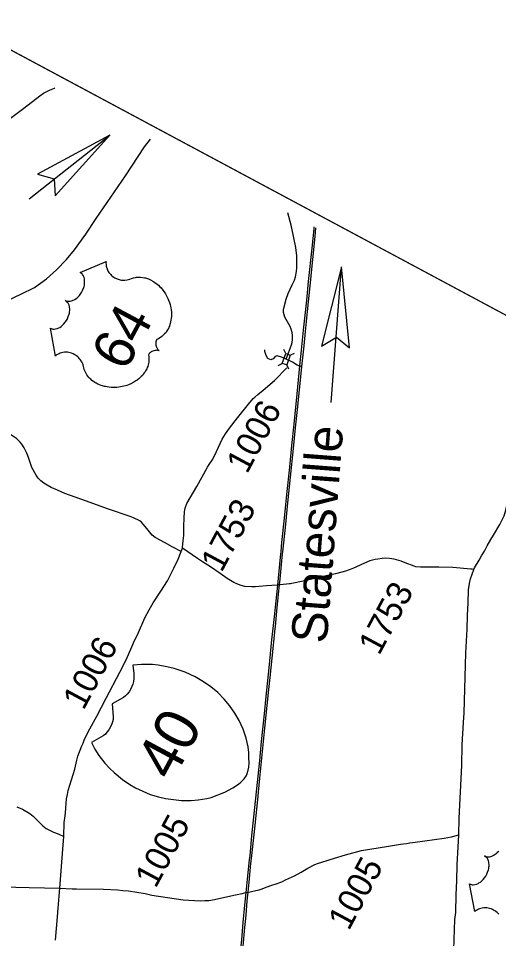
# Model space of a CAD drawing. Extents: x 1376167 to 1379209, y 761324 to 763997.
# Drawn here: x 1376691.6 to 1376772.1, y 762860.1 to 763014.5 of the extents above; entities that cross this region are included whole.
import ezdxf

# ---------------------------------------------------------------- set-up
doc = ezdxf.new("R2010")
doc.units = 0
for name, color, linetype in [('Default', 7, 'Continuous'), ('Old_Level_1', 7, 'Continuous'), ('Prop Terminator CELL', 7, 'Continuous'), ('Sheet Data Field CELL', 7, 'Continuous')]:
    doc.layers.add(name, color=color, linetype=linetype)

msp = doc.modelspace()

# ---------------------------------------------------------------- linework, layer by layer
at = {"layer": 'Default'}
for p, q in [((1376736.39, 762958.25), (1376736.05, 762958.96)), ((1376737.14, 762957.98), (1376737.85, 762958.33)), ((1376735.11, 762956.27), (1376735.82, 762956.62)), ((1376736.92, 762955.64), (1376736.58, 762956.35)), ((1376718.87, 762925.06), (1376719.07, 762925.6))]:
    msp.add_line(p, q, dxfattribs=at)
for points in [[(1376692.48, 762999.48), (1376695.16, 763001.54), (1376695.77, 763001.96), (1376696.79, 763002.5), (1376697.6, 763002.82)], [(1376697.6, 763002.82), (1376697.68, 763002.85)], [(1376672.6, 762984.28), (1376673.27, 762984.79), (1376675.3, 762986.31), (1376676.78, 762987.43), (1376677.83, 762988.21), (1376680.82, 762990.8), (1376686.12, 762994.69), (1376687.79, 762995.97), (1376692.48, 762999.48)], [(1376675.94, 762960.58), (1376682.69, 762963.88), (1376684.96, 762964.96), (1376691.99, 762968.25), (1376694.26, 762969.38), (1376696.28, 762970.78), (1376697.97, 762972.31), (1376699.64, 762974.04), (1376700.98, 762975.67), (1376702.88, 762978.32), (1376704.6, 762980.94), (1376709.52, 762988.1), (1376712.73, 762992.97), (1376713.7, 762994.26)], [(1376736.47, 762957.32), (1376736.87, 762958.38), (1376737.36, 762959.74), (1376737.46, 762960.14), (1376737.52, 762960.65), (1376737.54, 762961.29), (1376737.48, 762961.82), (1376737.31, 762962.36), (1376737.14, 762962.83), (1376736.27, 762964.35), (1376736.11, 762964.78), (1376736.04, 762965.14), (1376736.03, 762965.58), (1376736.07, 762965.9), (1376736.47, 762967.41), (1376736.78, 762968.34), (1376737.47, 762969.82), (1376737.88, 762970.59), (1376738.04, 762971.14), (1376738.2, 762972.06), (1376738.23, 762972.71), (1376738.25, 762974.66), (1376738.11, 762976.06), (1376737.7, 762977.99), (1376737.28, 762979.8), (1376736.75, 762981.9)], [(1376741.12, 762979.56), (1376741.09, 762979.19), (1376740.75, 762975.95), (1376740.18, 762970.34), (1376739.85, 762967.22), (1376739.34, 762962.17), (1376739, 762958.85), (1376738.72, 762956.18)], [(1376739.09, 762956.06), (1376739.46, 762959.54), (1376739.7, 762961.99), (1376740.03, 762965.35), (1376740.47, 762969.66), (1376740.92, 762974.05), (1376741.31, 762977.93), (1376741.46, 762979.38)], [(1376739.13, 762956.03), (1376738.59, 762956.18), (1376738.31, 762956.32), (1376737.52, 762956.8), (1376736.47, 762957.32), (1376735.83, 762957.61), (1376734.97, 762957.86), (1376734.6, 762957.78), (1376734.27, 762957.36), (1376733.92, 762957.2), (1376733.38, 762957.44), (1376733.1, 762957.92), (1376732.89, 762958.61), (1376732.9, 762958.9)], [(1376723.3, 762939.18), (1376723.57, 762939.64), (1376724.15, 762940.55), (1376724.79, 762941.85), (1376725.76, 762943.9), (1376726.3, 762944.79), (1376726.99, 762945.75), (1376728.28, 762947.48), (1376730.17, 762949.79), (1376730.91, 762950.7), (1376731.19, 762950.97), (1376731.73, 762951.38), (1376732.62, 762952.13), (1376734.49, 762953.74), (1376736.57, 762955.88)], [(1376738.72, 762956.18), (1376738.25, 762951.48), (1376737.73, 762946.42), (1376737.37, 762942.83), (1376737, 762939.18), (1376736.54, 762934.6), (1376736.13, 762930.65), (1376735.7, 762926.57), (1376735.55, 762925.07)], [(1376735.91, 762925.01), (1376736.36, 762929.09), (1376736.77, 762933.23), (1376737.2, 762937.51), (1376737.7, 762942.32), (1376738.04, 762945.81), (1376738.36, 762948.89), (1376738.7, 762952.16), (1376739.09, 762956.06)], [(1376769.23, 762924.3), (1376769.71, 762925.09), (1376770.16, 762925.99), (1376770.78, 762927.08), (1376771.24, 762927.77), (1376772.3, 762929.6), (1376773, 762931.02), (1376773.32, 762931.96), (1376774.06, 762935.28), (1376774.5, 762936.86), (1376774.93, 762938.19), (1376775.09, 762938.63), (1376775.39, 762939.28), (1376776.44, 762941.22), (1376776.84, 762942.22), (1376776.93, 762942.61), (1376777.01, 762943.15), (1376777.33, 762945.03), (1376777.55, 762946.64), (1376777.51, 762948.32), (1376777.32, 762949.87), (1376777.12, 762952.07)], [(1376698.1, 762935.36), (1376697.04, 762935.8), (1376696.37, 762936.16), (1376695.83, 762936.5), (1376695.33, 762936.88), (1376694.89, 762937.34), (1376694.52, 762937.85), (1376693.82, 762939.14), (1376693.32, 762940.63), (1376693.1, 762941.29), (1376692.94, 762941.66), (1376692.52, 762942.42), (1376692.15, 762943.04), (1376691.86, 762943.38), (1376691.61, 762943.63), (1376691.41, 762943.82), (1376691.23, 762943.99), (1376690.89, 762944.24), (1376690.28, 762944.6), (1376689.62, 762944.92), (1376687.2, 762945.84)], [(1376719.07, 762925.6), (1376719.1, 762925.79), (1376719.2, 762926.85), (1376719.28, 762927.72), (1376719.3, 762929.28), (1376719.34, 762930.63), (1376719.42, 762931.68), (1376719.45, 762932.02), (1376719.53, 762932.29), (1376719.65, 762932.66), (1376719.83, 762933.11), (1376721.46, 762935.97), (1376723.3, 762939.18)], [(1376718.87, 762925.06), (1376717.36, 762925.83), (1376716.05, 762926.58), (1376715.31, 762926.97), (1376714.5, 762927.4), (1376714.01, 762927.79), (1376713.1, 762928.91), (1376712.49, 762929.63), (1376712.23, 762929.94), (1376711.95, 762930.17), (1376710.89, 762930.71), (1376710.28, 762930.93), (1376706.69, 762932.16), (1376702.81, 762933.54), (1376699.36, 762934.76), (1376698.1, 762935.36)], [(1376710.58, 762909.04), (1376711.05, 762910.1), (1376711.53, 762911.07), (1376712.77, 762913.89), (1376713.47, 762915.24), (1376713.93, 762916.05), (1376714.18, 762916.45), (1376715.42, 762918.39), (1376716.57, 762920.1), (1376717.64, 762922.22), (1376718.35, 762923.78), (1376718.87, 762925.06)], [(1376729.55, 762919.18), (1376728.91, 762919.35), (1376728.17, 762919.61), (1376727.71, 762919.82), (1376726.59, 762920.52), (1376725.41, 762921.37), (1376723.77, 762922.47), (1376722.45, 762923.32), (1376721.58, 762923.87), (1376719.07, 762925.6)], [(1376735.55, 762925.07), (1376735.45, 762924.08), (1376734.99, 762919.41)], [(1376735.34, 762919.43), (1376735.45, 762920.42), (1376735.69, 762922.87), (1376735.87, 762924.64), (1376735.91, 762925.01)], [(1376750.52, 762923.49), (1376749.61, 762923.06), (1376748.26, 762922.48), (1376747.63, 762922.21), (1376746.43, 762921.74), (1376745.82, 762921.59), (1376744.74, 762921.32), (1376743.66, 762921.05), (1376739.31, 762920.09), (1376737.41, 762919.67), (1376737.2, 762919.62)], [(1376755.76, 762923.4), (1376754.57, 762923.77), (1376753.78, 762923.87), (1376753.16, 762923.9), (1376752.58, 762923.85), (1376751.86, 762923.75), (1376751.38, 762923.7), (1376750.52, 762923.49)], [(1376767.95, 762922.03), (1376767.64, 762922.07), (1376767.46, 762922.08), (1376764.44, 762922.36), (1376762.05, 762922.41), (1376760.56, 762922.4), (1376758.97, 762922.41), (1376758.23, 762922.48), (1376757.92, 762922.58), (1376756.44, 762923.13), (1376755.76, 762923.4)], [(1376767.95, 762922.03), (1376768.08, 762922.29), (1376768.81, 762923.58), (1376769.23, 762924.3)], [(1376765.44, 762877.48), (1376765.47, 762880.31), (1376765.9, 762889.15), (1376765.99, 762892.6), (1376766.23, 762896.35), (1376766.3, 762897.96), (1376766.62, 762907.96), (1376766.85, 762911.99), (1376766.87, 762914.3), (1376766.99, 762916.4), (1376767.06, 762918.6), (1376767.22, 762919.69), (1376767.39, 762920.43), (1376767.95, 762922.03)], [(1376733.17, 762919.27), (1376731.3, 762919.1), (1376730.64, 762919.1), (1376729.55, 762919.18)], [(1376734.99, 762919.41), (1376734.05, 762919.35), (1376733.17, 762919.27)], [(1376734.99, 762919.41), (1376734.72, 762916.74), (1376734.46, 762914.09)], [(1376734.65, 762912.47), (1376734.89, 762915.03), (1376735.2, 762917.88), (1376735.34, 762919.43)], [(1376735.34, 762919.43), (1376735.14, 762919.42), (1376734.99, 762919.41)], [(1376737.2, 762919.62), (1376737.04, 762919.6), (1376735.47, 762919.43), (1376735.34, 762919.43)], [(1376734.46, 762914.09), (1376734.02, 762910.24), (1376733.55, 762905.5), (1376733.06, 762900.7), (1376732.78, 762897.78), (1376732.3, 762893.14), (1376731.99, 762889.98), (1376731.43, 762884.7), (1376731.16, 762882.09), (1376730.68, 762877.33), (1376730.35, 762874.02), (1376730.28, 762873.29)], [(1376730.66, 762873.52), (1376731.14, 762878.03), (1376731.64, 762882.86), (1376732.04, 762886.98), (1376732.57, 762892.03), (1376732.91, 762895.4), (1376733.51, 762901.36), (1376733.77, 762903.87), (1376734.1, 762907.15), (1376734.61, 762912.07), (1376734.65, 762912.47)], [(1376704.71, 762897.39), (1376706.28, 762900.44), (1376708.58, 762904.77), (1376709.62, 762906.87), (1376710.58, 762909.04)], [(1376699.18, 762877.2), (1376699.22, 762879.53), (1376699.41, 762880.66), (1376699.44, 762881.2), (1376699.65, 762883.53), (1376699.77, 762884.26), (1376699.93, 762884.95), (1376701.01, 762888.5), (1376701.35, 762890.01), (1376701.54, 762890.67), (1376702.19, 762892.45), (1376702.41, 762892.89), (1376702.67, 762893.53), (1376703.53, 762895.3), (1376704.71, 762897.39)], [(1376691.32, 762882.19), (1376692.22, 762881.79), (1376693.46, 762881.09), (1376694.03, 762880.62), (1376695.64, 762878.99), (1376696.23, 762878.54), (1376697.43, 762877.93), (1376698.22, 762877.68), (1376699.18, 762877.2)], [(1376698.5, 762868.56), (1376698.96, 762874.33), (1376699.18, 762877.2)], [(1376758.08, 762876.23), (1376762.95, 762876.92), (1376764.19, 762877.16), (1376765.44, 762877.48)], [(1376764.9, 762864.43), (1376764.98, 762867.44), (1376765.08, 762869.76), (1376765.14, 762872.49), (1376765.33, 762875.42), (1376765.44, 762877.48)], [(1376741.28, 762872.48), (1376741.91, 762872.72), (1376743.2, 762873.13), (1376743.87, 762873.35), (1376746.4, 762874.12), (1376749.08, 762874.83), (1376749.77, 762874.97), (1376750.85, 762875.15), (1376753.31, 762875.54), (1376754.64, 762875.74), (1376755.65, 762875.91), (1376756.66, 762876.05), (1376757.19, 762876.12), (1376758.08, 762876.23)], [(1376772.15, 762864.15), (1376771.97, 762864.35), (1376771.83, 762864.47), (1376771.65, 762864.61), (1376771.48, 762864.74), (1376771.25, 762864.87), (1376771.06, 762864.97), (1376770.82, 762865.07), (1376770.58, 762865.14), (1376770.36, 762865.19), (1376770.1, 762865.23), (1376769.9, 762865.24), (1376769.62, 762865.23), (1376769.35, 762865.19), (1376769.11, 762865.14), (1376768.89, 762865.07), (1376768.7, 762864.99), (1376768.54, 762864.91), (1376768.35, 762864.8), (1376768.18, 762864.68), (1376768.09, 762864.6), (1376767.24, 762869.26), (1376767.38, 762869.2), (1376767.56, 762869.14), (1376767.65, 762869.12), (1376767.85, 762869.11), (1376768.11, 762869.14), (1376768.38, 762869.21), (1376768.65, 762869.32), (1376768.8, 762869.41), (1376769.04, 762869.56), (1376769.28, 762869.76), (1376769.51, 762870), (1376769.73, 762870.26), (1376769.93, 762870.55), (1376770.1, 762870.86), (1376770.26, 762871.21), (1376770.38, 762871.62), (1376770.43, 762871.81), (1376770.47, 762872.04), (1376770.49, 762872.25), (1376770.49, 762872.51), (1376770.47, 762872.72), (1376770.45, 762872.89), (1376770.38, 762873.15), (1376770.28, 762873.38), (1376770.21, 762873.49), (1376770.15, 762873.59), (1376769.99, 762873.76), (1376769.91, 762873.83), (1376769.74, 762873.94), (1376769.9, 762873.87), (1376770, 762873.83), (1376770.11, 762873.81), (1376770.22, 762873.79), (1376770.4, 762873.79), (1376770.56, 762873.8), (1376770.81, 762873.86), (1376770.94, 762873.9), (1376771.05, 762873.95), (1376771.32, 762874.09), (1376771.6, 762874.28), (1376771.72, 762874.38), (1376771.84, 762874.48), (1376771.98, 762874.62), (1376772.11, 762874.77)], [(1376730.28, 762873.29), (1376730, 762870.59), (1376729.71, 762867.79)], [(1376730.09, 762867.87), (1376730.26, 762869.54), (1376730.56, 762872.66), (1376730.66, 762873.52)], [(1376736.37, 762869.93), (1376737.85, 762870.58), (1376738.99, 762871.24), (1376740.12, 762871.89), (1376741.28, 762872.48)], [(1376733.28, 762868.76), (1376734.08, 762869.06), (1376734.79, 762869.27), (1376735.75, 762869.61), (1376736.37, 762869.93)], [(1376688.9, 762868.78), (1376693.37, 762868.65), (1376698.5, 762868.56)], [(1376697.79, 762859.81), (1376698.12, 762863.72), (1376698.24, 762865.18), (1376698.5, 762868.56)], [(1376698.5, 762868.56), (1376700.58, 762868.42), (1376701.28, 762868.41), (1376705.85, 762868.34), (1376708.24, 762868.28), (1376709.08, 762868.16)], [(1376709.08, 762868.16), (1376710.03, 762868.09), (1376712.83, 762867.62), (1376713.91, 762867.36)], [(1376727.71, 762867.35), (1376729.06, 762867.65), (1376729.71, 762867.79)], [(1376729.71, 762867.79), (1376729.5, 762865.7), (1376729.22, 762862.77)], [(1376729.64, 762862.95), (1376729.75, 762864.01), (1376729.94, 762866.43), (1376730.09, 762867.87)], [(1376729.71, 762867.79), (1376730.09, 762867.87)], [(1376730.09, 762867.87), (1376730.42, 762867.92), (1376731.4, 762868.14), (1376731.93, 762868.26), (1376732.25, 762868.34)], [(1376732.25, 762868.34), (1376733.28, 762868.76)], [(1376713.91, 762867.36), (1376719.19, 762866.55), (1376722.02, 762866.4)], [(1376722.02, 762866.4), (1376722.8, 762866.44), (1376723.5, 762866.48), (1376724.43, 762866.66), (1376727.67, 762867.34), (1376727.71, 762867.35)], [(1376728.07, 762847.79), (1376728.4, 762851), (1376728.89, 762855.62), (1376729.23, 762858.81), (1376729.53, 762861.94), (1376729.64, 762862.95)], [(1376764.07, 762844.96), (1376764.11, 762845.94), (1376764.15, 762848.53), (1376764.38, 762853.94), (1376764.51, 762856.01), (1376764.57, 762858.24), (1376764.77, 762863.25), (1376764.9, 762864.43)], [(1376729.22, 762862.77), (1376728.95, 762859.86), (1376728.48, 762855.31), (1376728.02, 762850.85), (1376727.7, 762847.61)]]:
    msp.add_lwpolyline(points, dxfattribs=at)
for points in [[(1376696.92, 762962.51), (1376697.06, 762962.45), (1376697.23, 762962.39), (1376697.33, 762962.37), (1376697.53, 762962.36), (1376697.78, 762962.39), (1376698.06, 762962.46), (1376698.32, 762962.57), (1376698.48, 762962.66), (1376698.72, 762962.81), (1376698.96, 762963.01), (1376699.19, 762963.25), (1376699.4, 762963.51), (1376699.61, 762963.8), (1376699.78, 762964.11), (1376699.93, 762964.46), (1376700.06, 762964.87), (1376700.11, 762965.06), (1376700.14, 762965.29), (1376700.17, 762965.5), (1376700.17, 762965.76), (1376700.15, 762965.97), (1376700.13, 762966.14), (1376700.05, 762966.4), (1376699.96, 762966.63), (1376699.89, 762966.74), (1376699.82, 762966.84), (1376699.66, 762967.01), (1376699.59, 762967.08), (1376699.41, 762967.19), (1376699.57, 762967.12), (1376699.68, 762967.08), (1376699.78, 762967.06), (1376699.9, 762967.04), (1376700.08, 762967.04), (1376700.23, 762967.05), (1376700.48, 762967.11), (1376700.62, 762967.15), (1376700.73, 762967.2), (1376701, 762967.34), (1376701.27, 762967.53), (1376701.4, 762967.63), (1376701.51, 762967.73), (1376701.65, 762967.87), (1376701.78, 762968.02), (1376701.9, 762968.18), (1376702.02, 762968.34), (1376702.13, 762968.51), (1376702.21, 762968.65), (1376702.31, 762968.83), (1376702.38, 762969), (1376702.45, 762969.17), (1376702.52, 762969.38), (1376702.57, 762969.54), (1376702.62, 762969.77), (1376702.65, 762969.98), (1376702.67, 762970.17), (1376702.67, 762970.43), (1376702.66, 762970.65), (1376702.63, 762970.82), (1376702.57, 762971.03), (1376702.49, 762971.25), (1376702.42, 762971.39), (1376702.33, 762971.51), (1376702.23, 762971.63), (1376702.12, 762971.73), (1376702.01, 762971.81), (1376701.92, 762971.87), (1376706.27, 762973.74), (1376706.26, 762973.64), (1376706.25, 762973.42), (1376706.26, 762973.23), (1376706.3, 762972.92), (1376706.33, 762972.78), (1376706.37, 762972.64), (1376706.42, 762972.5), (1376706.47, 762972.37), (1376706.55, 762972.2), (1376706.63, 762972.05), (1376706.74, 762971.89), (1376706.83, 762971.76), (1376707.04, 762971.52), (1376707.18, 762971.38), (1376707.3, 762971.28), (1376707.57, 762971.08), (1376707.71, 762971), (1376707.84, 762970.92), (1376707.99, 762970.85), (1376708.14, 762970.79), (1376708.3, 762970.74), (1376708.44, 762970.69), (1376708.61, 762970.65), (1376708.83, 762970.61), (1376709.04, 762970.59), (1376709.4, 762970.59), (1376709.8, 762970.62), (1376710.03, 762970.67), (1376710.24, 762970.73), (1376710.52, 762970.84), (1376710.68, 762970.9), (1376710.87, 762970.96), (1376711.22, 762971.04), (1376711.37, 762971.06), (1376711.54, 762971.08), (1376711.71, 762971.08), (1376711.89, 762971.09), (1376712.05, 762971.08), (1376712.39, 762971.05), (1376712.71, 762970.99), (1376712.87, 762970.95), (1376713.22, 762970.84), (1376713.39, 762970.78), (1376713.72, 762970.63), (1376714.1, 762970.43), (1376714.44, 762970.21), (1376714.83, 762969.92), (1376715.05, 762969.73), (1376715.29, 762969.48), (1376715.5, 762969.27), (1376715.79, 762968.92), (1376715.99, 762968.64), (1376716.22, 762968.3), (1376716.34, 762968.08), (1376716.48, 762967.83), (1376716.62, 762967.53), (1376716.76, 762967.2), (1376716.9, 762966.82), (1376716.99, 762966.52), (1376717.08, 762966.14), (1376717.12, 762965.92), (1376717.17, 762965.61), (1376717.21, 762965.2), (1376717.22, 762964.81), (1376717.22, 762964.49), (1376717.19, 762964.21), (1376717.15, 762963.86), (1376717.02, 762963.31), (1376716.97, 762963.12), (1376716.89, 762962.89), (1376716.8, 762962.69), (1376716.71, 762962.49), (1376716.57, 762962.24), (1376716.42, 762961.99), (1376716.26, 762961.77), (1376716.07, 762961.55), (1376715.85, 762961.33), (1376715.63, 762961.15), (1376715.39, 762960.97), (1376714.92, 762960.7), (1376714.79, 762960.62), (1376714.74, 762960.56), (1376714.65, 762960.41), (1376714.6, 762960.25), (1376714.58, 762960.06), (1376714.58, 762959.95), (1376714.59, 762959.78), (1376714.62, 762959.65), (1376714.66, 762959.48), (1376714.71, 762959.36), (1376714.75, 762959.26), (1376714.87, 762959.05), (1376714.93, 762958.97), (1376715.02, 762958.87), (1376715.16, 762958.74), (1376714.93, 762958.8), (1376714.76, 762958.81), (1376714.61, 762958.8), (1376714.47, 762958.79), (1376714.27, 762958.74), (1376714.12, 762958.69), (1376713.96, 762958.62), (1376713.81, 762958.54), (1376713.7, 762958.46), (1376713.61, 762958.38), (1376713.51, 762958.28), (1376713.46, 762958.19), (1376713.41, 762958.11), (1376713.38, 762957.99), (1376713.41, 762957.78), (1376713.43, 762957.59), (1376713.44, 762957.39), (1376713.44, 762957.15), (1376713.43, 762956.99), (1376713.41, 762956.8), (1376713.37, 762956.58), (1376713.32, 762956.35), (1376713.25, 762956.12), (1376713.18, 762955.92), (1376713.09, 762955.72), (1376713, 762955.54), (1376712.9, 762955.36), (1376712.8, 762955.19), (1376712.67, 762955.01), (1376712.5, 762954.78), (1376712.35, 762954.6), (1376712.17, 762954.41), (1376711.99, 762954.23), (1376711.77, 762954.04), (1376711.48, 762953.81), (1376711.26, 762953.66), (1376710.9, 762953.44), (1376710.43, 762953.2), (1376710.04, 762953.03), (1376709.74, 762952.93), (1376709.26, 762952.78), (1376708.95, 762952.71), (1376708.43, 762952.62), (1376708.06, 762952.59), (1376707.8, 762952.57), (1376707.39, 762952.57), (1376707.14, 762952.58), (1376706.78, 762952.61), (1376706.47, 762952.66), (1376706.17, 762952.71), (1376705.99, 762952.75), (1376705.68, 762952.84), (1376705.46, 762952.91), (1376705.17, 762953.02), (1376704.87, 762953.15), (1376704.6, 762953.29), (1376704.38, 762953.41), (1376704.14, 762953.58), (1376703.89, 762953.77), (1376703.69, 762953.94), (1376703.54, 762954.08), (1376703.38, 762954.26), (1376703.2, 762954.47), (1376703.04, 762954.7), (1376702.92, 762954.9), (1376702.79, 762955.13), (1376702.7, 762955.34), (1376702.61, 762955.61), (1376702.53, 762955.87), (1376702.49, 762956.1), (1376702.41, 762956.39), (1376702.35, 762956.55), (1376702.25, 762956.75), (1376702.16, 762956.92), (1376702.07, 762957.07), (1376701.93, 762957.27), (1376701.82, 762957.4), (1376701.64, 762957.6), (1376701.51, 762957.72), (1376701.33, 762957.86), (1376701.16, 762957.99), (1376700.93, 762958.12), (1376700.73, 762958.22), (1376700.49, 762958.32), (1376700.25, 762958.39), (1376700.04, 762958.44), (1376699.78, 762958.48), (1376699.58, 762958.49), (1376699.3, 762958.48), (1376699.02, 762958.44), (1376698.79, 762958.39), (1376698.56, 762958.32), (1376698.38, 762958.24), (1376698.21, 762958.16), (1376698.03, 762958.05), (1376697.86, 762957.93), (1376697.77, 762957.85)], [(1376735.82, 762956.62), (1376736.39, 762958.25), (1376737.15, 762957.98), (1376736.58, 762956.35)], [(1376729.79, 762887.43), (1376729.94, 762887.8), (1376730.1, 762888.32), (1376730.19, 762888.85), (1376730.24, 762889.5), (1376730.23, 762890.49), (1376730.2, 762891.31), (1376730.1, 762892.28), (1376729.74, 762893.71), (1376729.25, 762895.21), (1376728.56, 762896.67), (1376727.85, 762897.92), (1376726.94, 762899.17), (1376726.07, 762900.27), (1376724.98, 762901.37), (1376723.85, 762902.3), (1376722.61, 762903.14), (1376721.2, 762904.01), (1376719.5, 762904.79), (1376717.67, 762905.41), (1376716.48, 762905.7), (1376715.01, 762905.97), (1376714.03, 762906.06), (1376712.2, 762906.05), (1376710.74, 762905.95), (1376710.91, 762904.57), (1376710.9, 762903.72), (1376710.87, 762903.23), (1376710.73, 762902.77), (1376710.41, 762901.97), (1376710.14, 762901.5), (1376709.8, 762901.12), (1376709.52, 762900.79), (1376709.21, 762900.56), (1376707.28, 762899.5), (1376707.46, 762897.3), (1376707.43, 762896.87), (1376707.32, 762896.48), (1376707.23, 762896.09), (1376706.96, 762895.52), (1376706.71, 762895.1), (1376706.4, 762894.71), (1376706.14, 762894.4), (1376705.75, 762894.11), (1376703.8, 762893.01), (1376704.4, 762891.85), (1376705.05, 762890.81), (1376706.07, 762889.54), (1376706.91, 762888.64), (1376707.62, 762887.93), (1376709, 762886.79), (1376710.26, 762885.91), (1376711.2, 762885.37), (1376713.67, 762884.27), (1376715.08, 762883.85), (1376716.25, 762883.57), (1376718.94, 762883.26), (1376720.53, 762883.26), (1376721.73, 762883.35), (1376723.15, 762883.61), (1376723.86, 762883.78), (1376726.2, 762884.66), (1376727.54, 762885.36), (1376728.49, 762885.99), (1376728.87, 762886.32), (1376729.4, 762886.87)]]:
    msp.add_lwpolyline(points, close=True, dxfattribs=at)
at = {"layer": 'Old_Level_1'}
for points in [[(1376622.61, 762553.05), (1376345.79, 762701.47), (1376550.88, 763083.99), (1376827.7, 762935.57)], [(1376345.79, 762701.47), (1376660.36, 762532.81), (1376865.45, 762915.33), (1376550.88, 763083.99)]]:
    msp.add_lwpolyline(points, close=True, dxfattribs=at)
at = {"layer": 'Prop Terminator CELL'}
for points in [[(1376697.72, 762984.73), (1376706.9, 762994.9), (1376694.74, 762988.4), (1376697.58, 762987.58)], [(1376747.09, 762959.21), (1376745.77, 762972.84), (1376742.37, 762959.48), (1376744.89, 762961.02)]]:
    msp.add_lwpolyline(points, close=True, dxfattribs=at)
at = {"layer": 'Sheet Data Field CELL'}
for p, q in [((1376693.34, 762984.25), (1376706.9, 762994.9)), ((1376744.04, 762950.03), (1376745.77, 762972.84))]:
    msp.add_line(p, q, dxfattribs=at)

# ---------------------------------------------------------------- texts
at = {"layer": 'Default'}
for s, height, rotation, p in [('64', 6.801, 61.8015, (1376709.5, 762955.08)), ('Statesville', 6, 85.6346, (1376743.27, 762909.5)), ('40', 7.324, 61.8015, (1376717.4, 762886.29))]:
    msp.add_text(s, height=height, rotation=rotation, dxfattribs=at).set_placement(p)
at = {"layer": 'Old_Level_1'}
for s, p in [('1006', (1376729.91, 762937.93)), ('1753', (1376725.63, 762921.37)), ('1753', (1376752.06, 762907.46)), ('1006', (1376702.48, 762898.26)), ('1005', (1376714.58, 762868.37)), ('1005', (1376746.97, 762861.26))]:
    msp.add_text(s, height=4.185, rotation=61.8015, dxfattribs=at).set_placement(p)
at = {"layer": 'Sheet Data Field CELL'}
msp.add_text('          ALEXANDER          ', height=30, rotation=61.6702, dxfattribs=at).set_placement((1376533.71, 762878.93))

doc.saveas('drawing.dxf')
